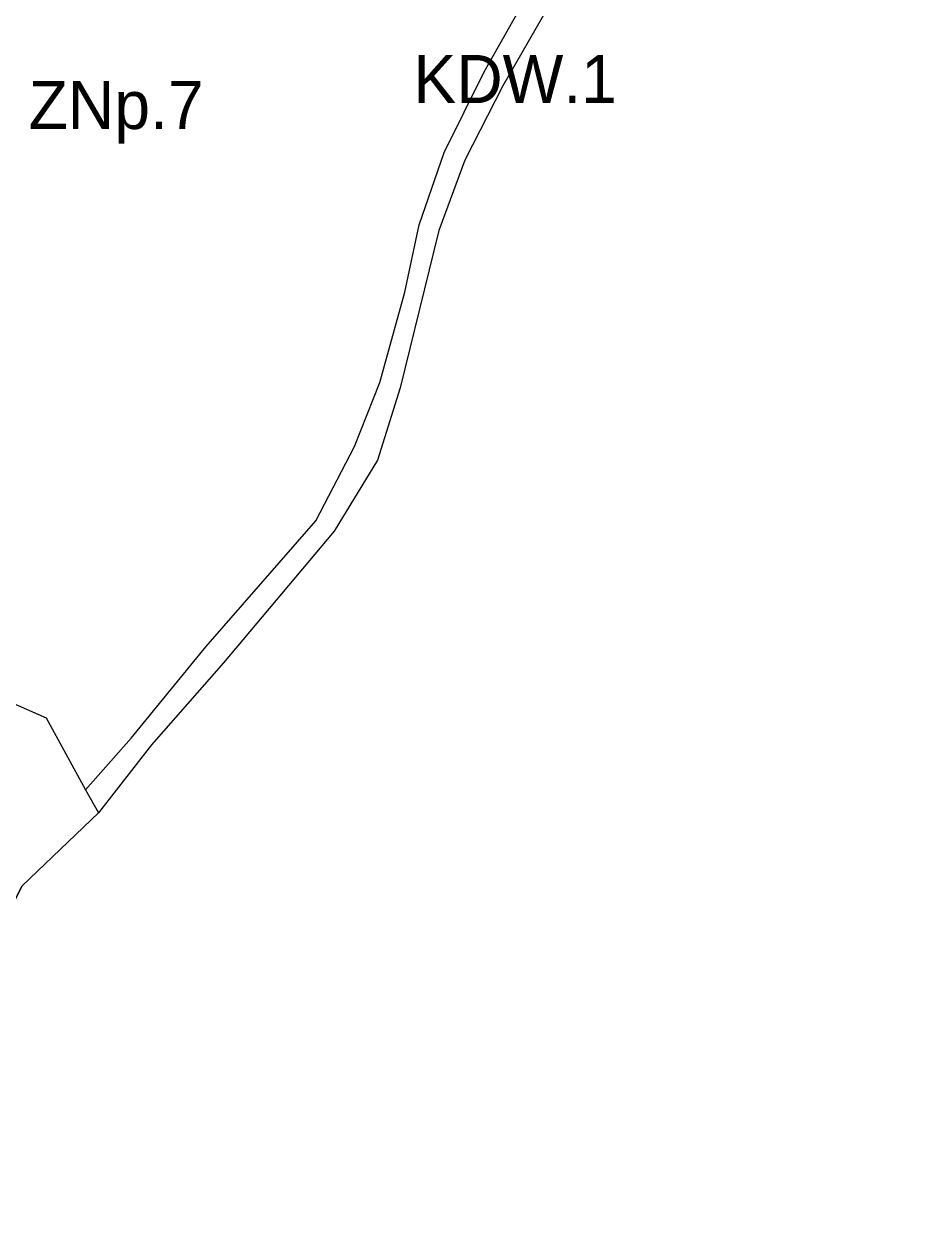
# Model space of a CAD drawing. Extents: x 7421614 to 7422630, y 5544623 to 5545754.
# Drawn here: x 7422192.7 to 7422379.2, y 5544920.4 to 5545170.9 of the extents above; entities that cross this region are included whole.
import ezdxf

# ---------------------------------------------------------------- set-up
doc = ezdxf.new("R2010")
doc.units = 0
for name, color, linetype in [('LIN_Granica Planu', 7, 'Continuous'), ('LIN_Linie Rozgraniczajace', 7, 'Continuous'), ('TXT_Oznaczenia Przeznaczenia', 7, 'Continuous')]:
    doc.layers.add(name, color=color, linetype=linetype)

msp = doc.modelspace()

# ---------------------------------------------------------------- linework, layer by layer
at = {"layer": 'LIN_Granica Planu'}
for p, q in [((7422284.38, 5545142.54), (7422278.94, 5545127.93)), ((7422219.2, 5545020.95), (7422208.14, 5545006.76))]:
    msp.add_line(p, q, dxfattribs=at)
for points in [[(7422316.17, 5545195.05), (7422301.74, 5545174.54), (7422292.28, 5545158.01), (7422284.38, 5545142.54)], [(7422278.94, 5545127.93), (7422270.92, 5545095.19), (7422266.15, 5545080.16), (7422257.17, 5545065.38), (7422234.12, 5545037.96), (7422219.2, 5545020.95)], [(7422208.14, 5545006.76), (7422192.24, 5544991.56), (7422177, 5544961.18), (7422166.21, 5544920.42)]]:
    msp.add_lwpolyline(points, dxfattribs=at)
at = {"layer": 'LIN_Linie Rozgraniczajace'}
for points in [[(7422379.22, 5545305.05), (7422368.51, 5545296.04), (7422346.72, 5545261.75), (7422339.71, 5545234.8), (7422332.36, 5545218.13), (7422316.17, 5545195.05), (7422301.74, 5545174.54), (7422292.28, 5545158.01), (7422284.38, 5545142.54), (7422278.94, 5545127.93), (7422270.92, 5545095.19), (7422266.15, 5545080.16), (7422257.17, 5545065.38), (7422234.12, 5545037.96), (7422219.2, 5545020.95), (7422208.14, 5545006.76)], [(7422205.48, 5545011.59), (7422214.94, 5545022.33), (7422230.51, 5545041.31), (7422253.33, 5545067.49), (7422261.4, 5545082.99), (7422266.67, 5545096.33), (7422271.86, 5545115.08), (7422274.82, 5545129.1), (7422280.04, 5545144.12), (7422288.34, 5545160.89), (7422297.62, 5545177.29)], [(7422149.25, 5544992.43), (7422148.95, 5545003.27), (7422151.09, 5545038.77), (7422166.95, 5545039.87), (7422197.24, 5545026.57), (7422205.48, 5545011.59)], [(7422205.48, 5545011.59), (7422208.14, 5545006.76)], [(7422166.21, 5544920.42), (7422177, 5544961.18), (7422187.77, 5544982.66), (7422192.24, 5544991.56), (7422208.14, 5545006.76)]]:
    msp.add_lwpolyline(points, dxfattribs=at)

# ---------------------------------------------------------------- texts
at = {"layer": 'TXT_Oznaczenia Przeznaczenia'}
for s, p in [('  KDW.1   ', (7422266.21, 5545154.43)), ('ZNp.7', (7422193.61, 5545149.03))]:
    msp.add_text(s, height=10, dxfattribs=at).set_placement(p)

doc.saveas('drawing.dxf')
